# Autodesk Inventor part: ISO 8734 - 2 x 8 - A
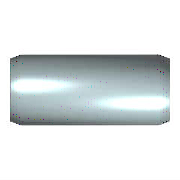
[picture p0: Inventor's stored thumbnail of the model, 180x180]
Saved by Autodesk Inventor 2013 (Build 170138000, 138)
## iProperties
Created: 2012-02
Part Number: ISO 8734 - 2 x 8 - A
Material: Steel
Description: Parallel Pin
Document SubType Name: Modeling
Standard: ISO 8734
Designer: rYan
Standards Organization: DIN
Language: en-US
Size Designation: 2 x 8 - A
Categories: <MemberInstance><Categories><Category DisplayName="Fasteners" InternalName="e4da775c-781d-43d5-af7c-5136215cf5a6" Mnemonic="FSTN"><Category DisplayName="Pins" I
Density: 7.85 g/cm^3
IsCustomPart: 0
Author: rYan
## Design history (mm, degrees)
sketch "Sketch"
  geometry: C1 r 1 at (0, 0); 1 further point
  constraints: 1 centre point, 1 coincident
  dimensions: "d1" = 2 diameter of C1 (= NND)
extrude "Body" new body sketch "Sketch" distance "d2" = 8 (= NLG); taper "d3" = 0 deg
body "Solid1"
chamfer "Chamfer1" distance "d4" = 0.35 (= PHH); stored, may be unused: angle "d5" = 15 deg (= FAWI), second distance "d11" = 0.35 (= PHH)
chamfer "Chamfer2" distance "d8" = 0.35 (= PHH); stored, may be unused: angle "d9" = 15 deg (= FAWI), second distance "d12" = 0.35 (= PHH)
other parameters: "NND" = 2 [user parameter; used in 1 equation term], "NLG" = 8 [user parameter; used in 1 equation term], "PHH" = 0.35 [user parameter; used in 5 equation terms], "FAWI" = 15 deg [user parameter; used in 2 equation terms], "d13" = 0, "d15" = 0, "d16" = 0, "PHH2" = 0.35 (= PHH) [user parameter], "FAWI2" = 15 deg [user parameter]
